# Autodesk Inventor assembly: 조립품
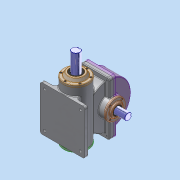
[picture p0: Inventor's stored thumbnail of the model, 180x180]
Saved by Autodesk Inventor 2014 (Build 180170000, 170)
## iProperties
Created: 2023-07
Part Number: 조립품
Document SubType Name: Assembly
Designer: dg
Author: dg
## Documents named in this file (14)
- C:\Users\dg\Desktop\730706V1013\조립품.iam
- C:\Users\dg\Desktop\730706V1013\본체.ipt
- C:\Users\dg\Desktop\730706V1013\웜 휠.ipt
- C:\Users\dg\Desktop\730706V1013\웜 샤프트.ipt
- C:\Users\dg\Desktop\730706V1013\깊은 홈 볼 베어링 6206.ipt
- C:\Users\dg\Desktop\730706V1013\앞커버.ipt
- C:\Users\dg\Desktop\730706V1013\뒤커버.ipt
- C:\Users\dg\Desktop\730706V1013\본체 커버.ipt
- C:\Users\dg\Desktop\730706V1013\서브커버.ipt
- C:\Users\dg\Desktop\730706V1013\육각 소켓 머리 볼트 M6 x 20.ipt
- C:\Users\dg\Desktop\730706V1013\육각 소켓 머리 볼트 M5 x 12.ipt
- C:\Users\dg\Desktop\730706V1013\깊은 홈 볼 베어링 6209.ipt
- C:\Users\dg\Desktop\730706V1013\오일 실 30 42 7.ipt
- C:\Users\dg\Desktop\730706V1013\오일 실 35 55 11.ipt
